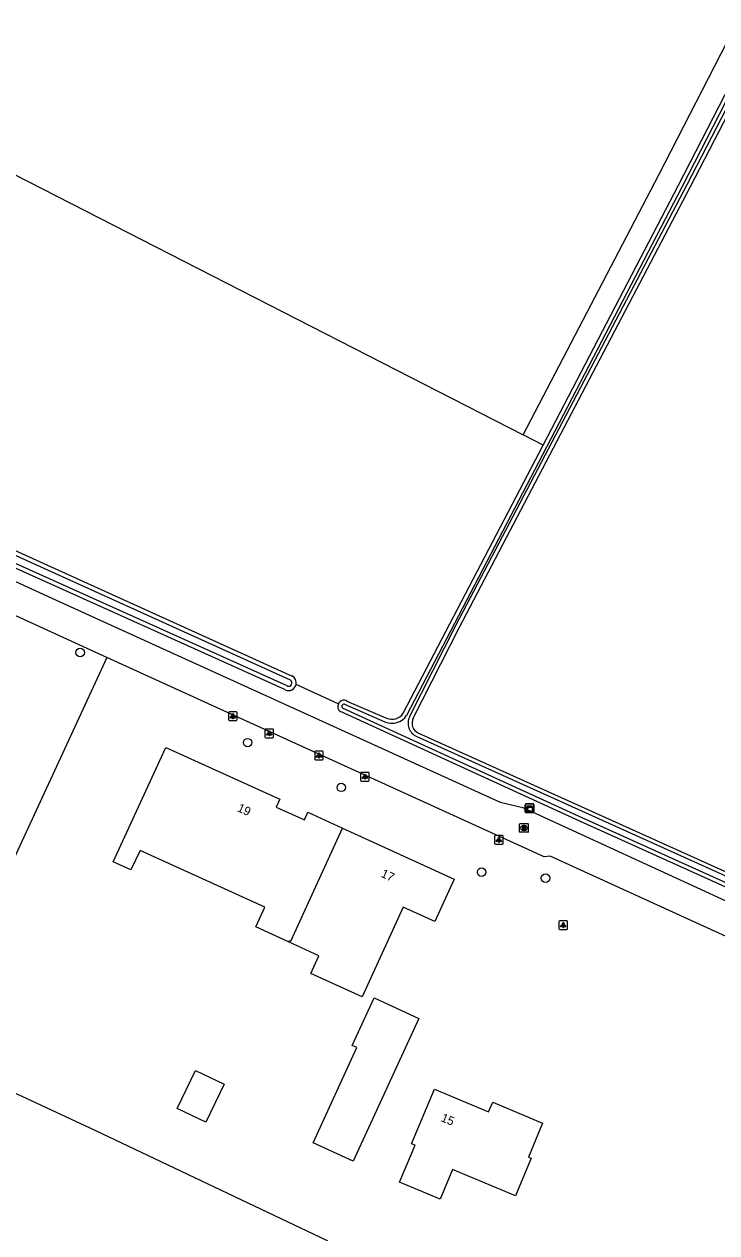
# Model space of a CAD drawing. Extents: x 155209 to 156823, y 385356 to 388482.
# Drawn here: x 155777.4 to 155857.2, y 385979.6 to 386118.8 of the extents above; entities that cross this region are included whole.
import ezdxf

# ---------------------------------------------------------------- set-up
doc = ezdxf.new("R2010")
doc.units = 0
for name, color, linetype in [('IMGEO_Boom', 7, 'Continuous'), ('IMGEO_Grasland_agrarisch', 7, 'Continuous'), ('IMGEO_Grasland_overig', 7, 'Continuous'), ('IMGEO_Groenvoorziening', 7, 'Continuous'), ('IMGEO_Kast', 7, 'Continuous'), ('IMGEO_Lichtpunt', 7, 'Continuous'), ('IMGEO_Loofbos', 7, 'Continuous'), ('IMGEO_Pand', 7, 'Continuous'), ('IMGEO_Pand_nummerreeks', 7, 'Continuous'), ('IMGEO_Rijbaan_lokaal_open', 7, 'Continuous'), ('IMGEO_Rioolput', 7, 'Continuous'), ('IMGEO_Waterloop', 7, 'Continuous')]:
    doc.layers.add(name, color=color, linetype=linetype)

msp = doc.modelspace()

# ---------------------------------------------------------------- linework, layer by layer
at = {"layer": 'IMGEO_Boom'}
for centre in [(155783.88, 386046.46), (155803.17, 386036.08), (155813.96, 386030.92), (155830.12, 386021.16), (155837.48, 386020.46)]:
    msp.add_circle(centre, 0.489, dxfattribs=at)
at = {"layer": 'IMGEO_Grasland_agrarisch'}
msp.add_lwpolyline([(155765.9, 386000.59), (155785.57, 385991.44), (155812.34, 385978.74), (155809.88, 385972.63), (155808.05, 385968.03), (155801.87, 385953.41)], dxfattribs=at)
at = {"layer": 'IMGEO_Grasland_overig'}
for points in [[(155834.92, 386071.53), (155850.53, 386101.48), (155869.89, 386139.18), (155897.23, 386193.45), (155910.33, 386221.05), (155911.39, 386223.4)], [(155837.21, 386070.36), (155852.82, 386100.29), (155872.18, 386138.01), (155899.55, 386192.32), (155913.61, 386221.94)], [(155786.93, 386045.9), (155786.05, 386043.98), (155767.96, 386004.93), (155765.9, 386000.59)]]:
    msp.add_lwpolyline(points, dxfattribs=at)
at = {"layer": 'IMGEO_Groenvoorziening'}
for points in [[(155807.53, 386042.14), (155738.44, 386073.25)], [(155916.27, 385993.23), (155901.28, 386000), (155841.09, 386027.17), (155813.87, 386039.65)]]:
    msp.add_lwpolyline(points, dxfattribs=at)
for centre, radius, start, end in [((155807.87, 386042.96), 0.894, 247.102, 347.1497), ((155814.26, 386040.25), 0.711, 154.8939, 237.4164)]:
    msp.add_arc(centre, radius, start, end, dxfattribs=at)
at = {"layer": 'IMGEO_Kast'}
for p, q in [((155835.14, 386028.09), (155835.14, 386028.93)), ((155835.14, 386028.93), (155835.14, 386028.09)), ((155835.21, 386029.01), (155836.06, 386029.01)), ((155836.06, 386029.01), (155835.21, 386029.01)), ((155836.07, 386028.01), (155835.22, 386028.01)), ((155835.22, 386028.01), (155836.07, 386028.01)), ((155836.14, 386028.94), (155836.14, 386028.1)), ((155836.14, 386028.1), (155836.14, 386028.94))]:
    msp.add_line(p, q, dxfattribs=at)
for points in [[(155835.34, 386028.8), (155835.94, 386028.8), (155835.94, 386028.72), (155835.34, 386028.72), (155835.34, 386028.8)], [(155835.34, 386028.63), (155835.94, 386028.63), (155835.94, 386028.14), (155835.34, 386028.14), (155835.34, 386028.63)]]:
    msp.add_lwpolyline(points, dxfattribs=at)
msp.add_circle((155835.42, 386028.48), 0.0377, dxfattribs=at)
for centre, start, end in [((155835.22, 386028.94), 92.4484, 184.2845), ((155835.22, 386028.94), 92.4484, 184.2845), ((155835.22, 386028.09), 182.4484, 274.2845), ((155835.22, 386028.09), 182.4484, 274.2845), ((155836.06, 386028.94), 2.4484, 94.2845), ((155836.06, 386028.94), 2.4484, 94.2845), ((155836.06, 386028.09), 272.4484, 4.2845), ((155836.06, 386028.09), 272.4484, 4.2845)]:
    msp.add_arc(centre, 0.0779, start, end, dxfattribs=at)
at = {"layer": 'IMGEO_Lichtpunt'}
for p, q in [((155800.97, 386039.53), (155800.97, 386038.73)), ((155800.97, 386039.53), (155800.97, 386038.73)), ((155801.87, 386039.63), (155801.06, 386039.63)), ((155801.87, 386039.63), (155801.06, 386039.63)), ((155801.97, 386038.73), (155801.97, 386039.53)), ((155801.97, 386038.73), (155801.97, 386039.53)), ((155801.06, 386038.63), (155801.87, 386038.63)), ((155801.06, 386038.63), (155801.87, 386038.63)), ((155805.15, 386037.55), (155805.15, 386036.74)), ((155805.15, 386037.55), (155805.15, 386036.74)), ((155806.06, 386037.64), (155805.25, 386037.64)), ((155806.06, 386037.64), (155805.25, 386037.64)), ((155806.15, 386036.74), (155806.15, 386037.55)), ((155806.15, 386036.74), (155806.15, 386037.55)), ((155805.25, 386036.64), (155806.06, 386036.64)), ((155805.25, 386036.64), (155806.06, 386036.64)), ((155810.89, 386034.99), (155810.89, 386034.19)), ((155810.89, 386034.99), (155810.89, 386034.19)), ((155811.79, 386035.09), (155810.98, 386035.09)), ((155811.79, 386035.09), (155810.98, 386035.09)), ((155811.88, 386034.19), (155811.88, 386034.99)), ((155811.88, 386034.19), (155811.88, 386034.99)), ((155810.98, 386034.09), (155811.79, 386034.09)), ((155810.98, 386034.09), (155811.79, 386034.09)), ((155816.18, 386032.56), (155816.18, 386031.75)), ((155816.18, 386032.56), (155816.18, 386031.75)), ((155817.08, 386032.65), (155816.27, 386032.65)), ((155817.08, 386032.65), (155816.27, 386032.65)), ((155817.17, 386031.75), (155817.17, 386032.56)), ((155817.17, 386031.75), (155817.17, 386032.56)), ((155816.27, 386031.65), (155817.08, 386031.65)), ((155816.27, 386031.65), (155817.08, 386031.65)), ((155831.62, 386025.27), (155831.62, 386024.47)), ((155831.62, 386025.27), (155831.62, 386024.47)), ((155832.52, 386025.37), (155831.71, 386025.37)), ((155832.52, 386025.37), (155831.71, 386025.37)), ((155832.62, 386024.47), (155832.62, 386025.27)), ((155832.62, 386024.47), (155832.62, 386025.27)), ((155831.71, 386024.37), (155832.52, 386024.37)), ((155831.71, 386024.37), (155832.52, 386024.37)), ((155839.03, 386015.46), (155839.03, 386014.66)), ((155839.03, 386015.46), (155839.03, 386014.66)), ((155839.93, 386015.56), (155839.12, 386015.56)), ((155839.93, 386015.56), (155839.12, 386015.56)), ((155840.02, 386014.66), (155840.02, 386015.46)), ((155840.02, 386014.66), (155840.02, 386015.46)), ((155839.12, 386014.56), (155839.93, 386014.56)), ((155839.12, 386014.56), (155839.93, 386014.56))]:
    msp.add_line(p, q, dxfattribs=at)
for points in [[(155801.34, 386039.2), (155801.38, 386039.17), (155801.19, 386038.91), (155801.16, 386038.94), (155801.34, 386039.2)], [(155801.44, 386039.15), (155801.49, 386039.15), (155801.49, 386038.83), (155801.44, 386038.83), (155801.44, 386039.15)], [(155801.55, 386039.17), (155801.59, 386039.2), (155801.78, 386038.93), (155801.74, 386038.91), (155801.55, 386039.17)], [(155805.53, 386037.21), (155805.57, 386037.18), (155805.38, 386036.92), (155805.34, 386036.95), (155805.53, 386037.21)], [(155805.63, 386037.16), (155805.68, 386037.16), (155805.68, 386036.84), (155805.63, 386036.84), (155805.63, 386037.16)], [(155805.74, 386037.18), (155805.78, 386037.21), (155805.97, 386036.95), (155805.93, 386036.92), (155805.74, 386037.18)], [(155811.26, 386034.66), (155811.3, 386034.63), (155811.11, 386034.37), (155811.07, 386034.39), (155811.26, 386034.66)], [(155811.36, 386034.61), (155811.41, 386034.61), (155811.41, 386034.29), (155811.36, 386034.29), (155811.36, 386034.61)], [(155811.47, 386034.63), (155811.51, 386034.66), (155811.7, 386034.39), (155811.66, 386034.37), (155811.47, 386034.63)], [(155816.55, 386032.22), (155816.59, 386032.19), (155816.4, 386031.93), (155816.36, 386031.96), (155816.55, 386032.22)], [(155816.65, 386032.17), (155816.7, 386032.17), (155816.7, 386031.85), (155816.65, 386031.85), (155816.65, 386032.17)], [(155816.76, 386032.19), (155816.8, 386032.22), (155816.99, 386031.96), (155816.95, 386031.93), (155816.76, 386032.19)], [(155831.99, 386024.94), (155832.03, 386024.91), (155831.84, 386024.65), (155831.81, 386024.67), (155831.99, 386024.94)], [(155832.09, 386024.89), (155832.14, 386024.89), (155832.14, 386024.57), (155832.09, 386024.57), (155832.09, 386024.89)], [(155832.2, 386024.91), (155832.24, 386024.94), (155832.43, 386024.67), (155832.39, 386024.65), (155832.2, 386024.91)], [(155839.4, 386015.13), (155839.44, 386015.1), (155839.25, 386014.84), (155839.21, 386014.87), (155839.4, 386015.13)], [(155839.5, 386015.08), (155839.55, 386015.08), (155839.55, 386014.76), (155839.5, 386014.76), (155839.5, 386015.08)], [(155839.61, 386015.1), (155839.65, 386015.13), (155839.84, 386014.86), (155839.8, 386014.84), (155839.61, 386015.1)]]:
    msp.add_lwpolyline(points, dxfattribs=at)
for centre in [(155801.47, 386039.33), (155805.65, 386037.34), (155811.39, 386034.79), (155816.68, 386032.35), (155832.12, 386025.07), (155839.53, 386015.26)]:
    msp.add_circle(centre, 0.0994, dxfattribs=at)
for centre, start, end in [((155801.06, 386039.53), 90, 180), ((155801.06, 386039.53), 90, 180), ((155801.87, 386039.53), 0, 90), ((155801.87, 386039.53), 0, 90), ((155801.06, 386038.73), 180, 270), ((155801.06, 386038.73), 180, 270), ((155801.87, 386038.73), 270, 0), ((155801.87, 386038.73), 270, 360), ((155805.25, 386037.55), 90, 180), ((155805.25, 386037.55), 90, 180), ((155806.06, 386037.55), 0, 90), ((155806.06, 386037.55), 0, 90), ((155805.25, 386036.74), 180, 270), ((155805.25, 386036.74), 180, 270), ((155806.06, 386036.74), 270, 0), ((155806.06, 386036.74), 270, 360), ((155810.98, 386034.99), 90, 180), ((155810.98, 386034.99), 90, 180), ((155811.79, 386034.99), 0, 90), ((155811.79, 386034.99), 0, 90), ((155810.98, 386034.19), 180, 270), ((155810.98, 386034.19), 180, 270), ((155811.79, 386034.19), 270, 0), ((155811.79, 386034.19), 270, 360), ((155816.27, 386032.56), 90, 180), ((155816.27, 386032.56), 90, 180), ((155817.08, 386032.56), 0, 90), ((155817.08, 386032.56), 0, 90), ((155816.27, 386031.75), 180, 270), ((155816.27, 386031.75), 180, 270), ((155817.08, 386031.75), 270, 0), ((155817.08, 386031.75), 270, 360), ((155831.71, 386025.27), 90, 180), ((155831.71, 386025.27), 90, 180), ((155832.52, 386025.27), 0, 90), ((155832.52, 386025.27), 0, 90), ((155831.71, 386024.47), 180, 270), ((155831.71, 386024.47), 180, 270), ((155832.52, 386024.47), 270, 0), ((155832.52, 386024.47), 270, 360), ((155839.12, 386015.46), 90, 180), ((155839.12, 386015.46), 90, 180), ((155839.93, 386015.46), 0, 90), ((155839.93, 386015.46), 0, 90), ((155839.12, 386014.66), 180, 270), ((155839.12, 386014.66), 180, 270), ((155839.93, 386014.66), 270, 0), ((155839.93, 386014.66), 270, 360)]:
    msp.add_arc(centre, 0.0946, start, end, dxfattribs=at)
at = {"layer": 'IMGEO_Loofbos'}
for points in [[(155822.24, 386038.89), (155827.56, 386049.39), (155854.18, 386100.13), (155871.23, 386133.09), (155899.02, 386188.41), (155914.94, 386221.5), (155915.31, 386221.64), (155995.42, 386186.63), (155996.15, 386188.3), (155914.38, 386224.1), (155912.74, 386224.24), (155875.07, 386241.03), (155857.11, 386250), (155838.57, 386259.27), (155825.81, 386265.2)], [(155728.14, 386080.19), (155746.94, 386116.53), (155834.92, 386071.53)], [(155739.12, 386074.85), (155770.1, 386061.03), (155808.28, 386043.75)], [(155837.21, 386070.36), (155834.92, 386071.53)], [(155821.1, 386039.46), (155837.21, 386070.36)], [(155813.61, 386040.55), (155808.75, 386042.76)], [(155814.61, 386040.87), (155819.17, 386038.89)], [(155883.66, 386009.73), (155822.83, 386037.18)]]:
    msp.add_lwpolyline(points, dxfattribs=at)
for centre, radius, start, end in [((155807.87, 386042.96), 0.896, 347.2846, 62.7618), ((155814.26, 386040.25), 0.71, 60.5107, 155.0748), ((155819.79, 386040.34), 1.58, 246.7052, 325.981), ((155823.35, 386038.32), 1.25, 153.0576, 245.6959)]:
    msp.add_arc(centre, radius, start, end, dxfattribs=at)
at = {"layer": 'IMGEO_Pand'}
for points in [[(155807.89, 386013.12), (155804.11, 386014.84), (155805.15, 386017.11), (155790.77, 386023.67), (155789.73, 386021.41), (155787.68, 386022.34), (155793.73, 386035.53), (155806.86, 386029.55), (155806.45, 386028.65), (155809.73, 386027.2), (155810.11, 386028.08), (155814.1, 386026.24)], [(155807.89, 386013.12), (155807.97, 386013.29), (155808.14, 386013.21), (155814.1, 386026.24)], [(155814.1, 386026.24), (155826.96, 386020.35), (155824.75, 386015.47), (155821.08, 386017.11), (155816.36, 386006.79), (155810.44, 386009.49), (155811.38, 386011.53), (155807.89, 386013.12)], [(155815.33, 385987.87), (155810.71, 385989.99), (155815.73, 386000.94), (155815.21, 386001.18), (155817.73, 386006.67), (155822.88, 386004.31), (155815.33, 385987.87)], [(155795.06, 385993.93), (155797.16, 385998.31), (155800.45, 385996.74), (155798.36, 385992.35), (155795.06, 385993.93)], [(155825.33, 385983.48), (155820.67, 385985.43), (155822.46, 385989.7), (155822.05, 385989.87), (155824.68, 385996.15), (155830.93, 385993.53), (155831.4, 385994.67), (155837.15, 385992.26), (155835.51, 385988.34), (155835.83, 385988.2), (155834.01, 385983.87), (155826.78, 385986.91), (155825.33, 385983.48)]]:
    msp.add_lwpolyline(points, dxfattribs=at)
at = {"layer": 'IMGEO_Rijbaan_lokaal_open'}
for points in [[(155736.9, 386072.88), (155759.83, 386062.69), (155766.03, 386059.41), (155780.61, 386052.71), (155832.25, 386029.22), (155834.86, 386028.6), (155915.05, 385991.74)], [(155786.93, 386045.9), (155774.57, 386051.53)], [(155873.35, 386006.89), (155838.02, 386023), (155837.33, 386022.91), (155786.93, 386045.9)]]:
    msp.add_lwpolyline(points, dxfattribs=at)
at = {"layer": 'IMGEO_Rioolput'}
for p, q in [((155834.5, 386025.82), (155834.5, 386026.68)), ((155834.58, 386026.75), (155835.43, 386026.75)), ((155834.99, 386026.53), (155835.02, 386026.53)), ((155835.5, 386026.68), (155835.5, 386025.82)), ((155835.43, 386025.75), (155834.58, 386025.75)), ((155835.01, 386025.97), (155834.99, 386025.97))]:
    msp.add_line(p, q, dxfattribs=at)
for points in [[(155834.5, 386025.82), (155834.5, 386026.68)], [(155834.58, 386026.75), (155835.43, 386026.75)], [(155835.09, 386026.45), (155834.84, 386026.45), (155834.84, 386026.05)], [(155835.5, 386026.68), (155835.5, 386025.82)], [(155835.43, 386025.75), (155834.58, 386025.75)], [(155834.84, 386026.05), (155834.96, 386026.05), (155834.96, 386026.21), (155834.98, 386026.21)], [(155835.02, 386026.37), (155834.96, 386026.37), (155834.96, 386026.29)], [(155834.96, 386026.29), (155835.02, 386026.29)], [(155835.02, 386026.18), (155835.09, 386026.05), (155835.23, 386026.05), (155835.17, 386026.18)]]:
    msp.add_lwpolyline(points, dxfattribs=at)
for centre, radius, start, end in [((155834.58, 386026.67), 0.0765, 91.552, 178.448), ((155834.58, 386026.67), 0.0765, 91.552, 178.448), ((155835.09, 386026.34), 0.109, 350.3612, 89.416), ((155835.43, 386026.67), 0.0765, 1.552, 88.448), ((155835.43, 386026.67), 0.0765, 1.552, 88.448), ((155834.58, 386025.82), 0.0765, 181.552, 268.448), ((155834.58, 386025.82), 0.0765, 181.552, 268.448), ((155834.97, 386026.16), 0.0533, 26.0293, 88.6989), ((155835.02, 386026.27), 0.0964, 77.0061, 93.1865), ((155835, 386026.48), 0.19, 274.7715, 282.9687), ((155835.04, 386026.33), 0.0378, 276.6634, 79.6772), ((155835.09, 386026.34), 0.112, 277.5842, 350.9817), ((155835.07, 386026.12), 0.108, 29.5134, 73.7905), ((155835.43, 386025.82), 0.0765, 271.552, 358.448), ((155835.43, 386025.82), 0.0765, 271.552, 358.448)]:
    msp.add_arc(centre, radius, start, end, dxfattribs=at)
for centre, major_axis, ratio, start_param, end_param in [((155834.99, 386026.25), (-0.387, 0.002), 0.722429, 4.712389, 7.853982), ((155835.01, 386026.25), (-0.39, 0.002), 0.717154, 1.570796, 4.712389)]:
    msp.add_ellipse(centre, major_axis=major_axis, ratio=ratio, start_param=start_param, end_param=end_param, dxfattribs=at)
at = {"layer": 'IMGEO_Waterloop'}
for points in [[(155825.61, 386264.79), (155838.37, 386258.86), (155856.91, 386249.6), (155874.87, 386240.62), (155912.62, 386223.8), (155914.26, 386223.65), (155995.54, 386188.08), (155995.17, 386187.24), (155915.32, 386222.13), (155914.61, 386221.86), (155898.62, 386188.61), (155870.82, 386133.3), (155853.78, 386100.34), (155827.16, 386049.6), (155821.83, 386039.09)], [(155821.49, 386039.23), (155837.62, 386070.15), (155853.22, 386100.09), (155872.59, 386137.8), (155899.96, 386192.12), (155914.02, 386221.75)], [(155738.96, 386074.38), (155769.89, 386060.57), (155808.06, 386043.3)], [(155807.73, 386042.6), (155738.68, 386073.7)], [(155814.32, 386040.5), (155818.99, 386038.47)], [(155885.99, 386008.33), (155905.49, 385999.59), (155915.28, 385995.19), (155914.9, 385994.35), (155901.47, 386000.41), (155841.28, 386027.59), (155814.1, 386040.05)], [(155822.65, 386036.77), (155883.47, 386009.32)]]:
    msp.add_lwpolyline(points, dxfattribs=at)
for centre, radius, start, end in [((155807.87, 386042.96), 0.393, 247.6127, 61.5422), ((155814.26, 386040.25), 0.26, 76.6054, 231.9822), ((155819.79, 386040.34), 2.03, 246.6263, 326.768), ((155823.35, 386038.32), 1.7, 153.1574, 245.715)]:
    msp.add_arc(centre, radius, start, end, dxfattribs=at)

# ---------------------------------------------------------------- texts
at = {"layer": 'IMGEO_Pand_nummerreeks'}
for s, rotation, p in [('19', 335.4911, (155801.89, 386028.21)), ('17', 335.3568, (155818.44, 386020.65)), ('15', 337.312, (155825.35, 385992.5))]:
    msp.add_text(s, height=1, rotation=rotation, dxfattribs=at).set_placement(p)

doc.saveas('drawing.dxf')
